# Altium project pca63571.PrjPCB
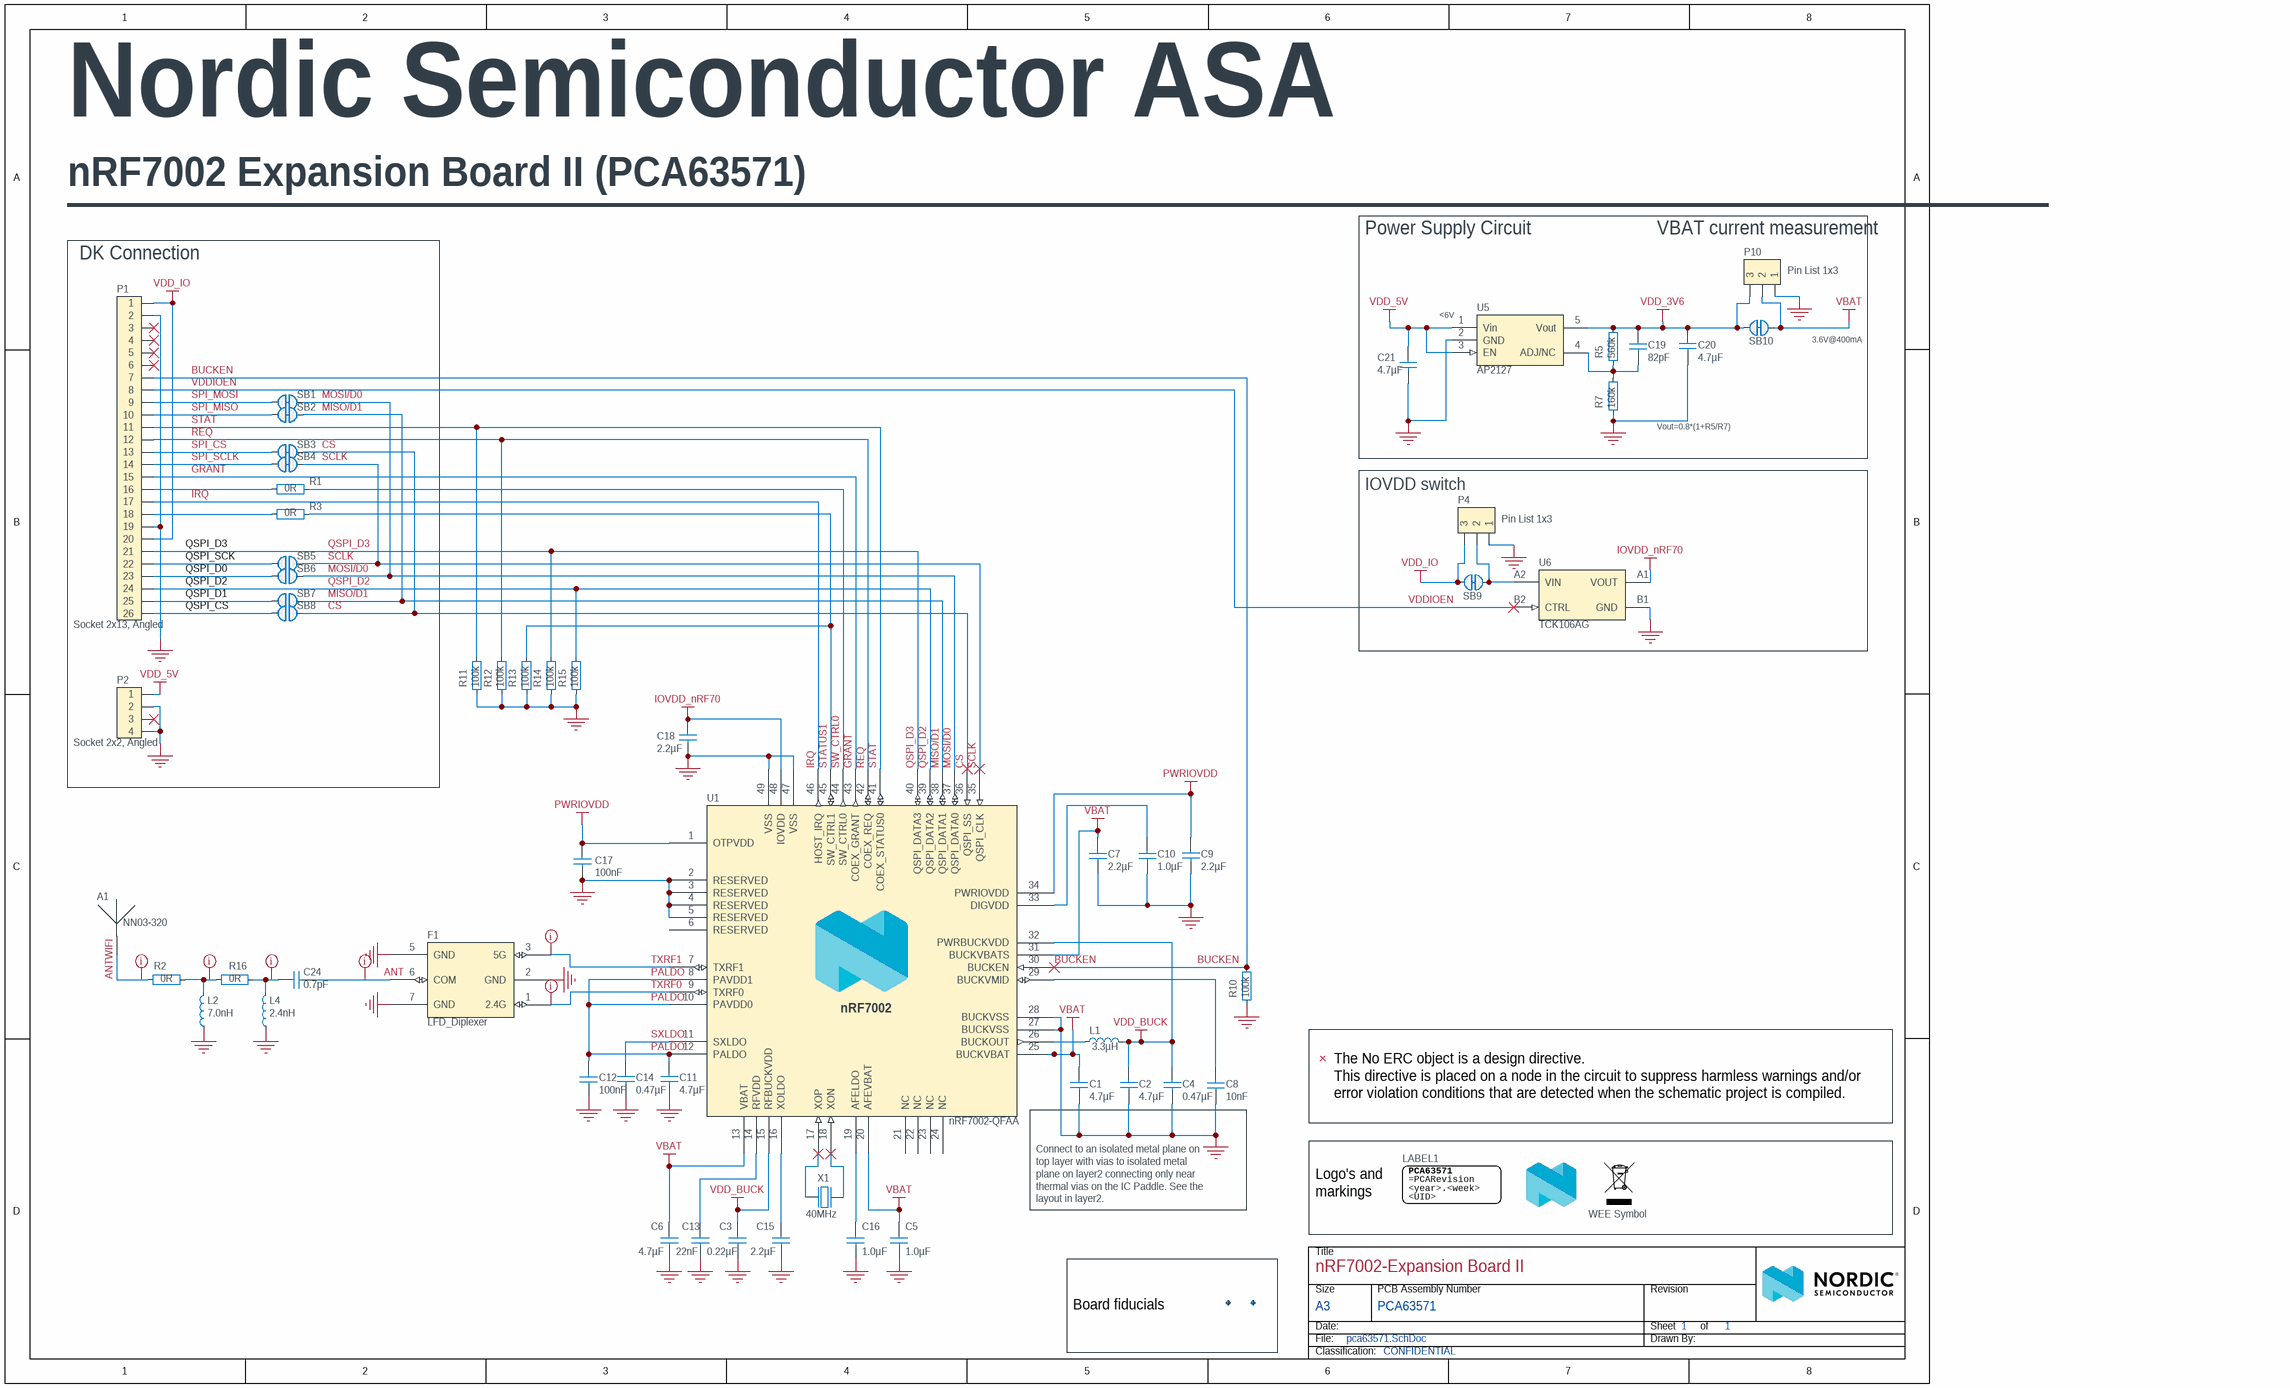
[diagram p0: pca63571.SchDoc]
BoardThickness: 1.6mm; BoardTitle: nRF7002 Expansion Board II; Classification: CONFIDENTIAL; Compliance: RoHS, REACH, Halogen-Free; Designer: HANY; Dielectric: FR-4; NrOfLayers: 4; Organization: Nordic Semiconductor; PCAName: PCA63571; PCARevision: 0.5.0; PCBNumber: 400902; PCBRevision: 0069HANY; PCBStackup: 4001; ProductName: nRF7002-EB2; ProjectName: nRF7002 EXpansion Board II; ProjectNumber: 4486; SilkscreenColor: White; SoldermaskColor: Blue; SurfaceFinish: ENIG Gold
1 sheet, 62 parts. Net scope: global (net labels, ports and power ports of the same name join across sheets).
Board files: 400902.PcbDoc, 400902_panel.PcbDoc

## Sheet pca63571.SchDoc: nRF7002-Expansion Board II
size A3; Organization: Nordic Semiconductor; Revision: 0.5.0; SheetNumber: 1; SheetTotal: 1; Author: HANY; CompanyName: Nordic Semiconductor; DrawnBy: HANY; DocumentSize: A4

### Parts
A1  NN03-320  [NN03-320]
C1  4.7µF  [CAPC1608X06L]
C2  4.7µF  [CAPC1608X06L]
C3  0.22µF  [CAPC0603X03L_C]
C4  0.47µF  [CAPC0603X03L_C]
C5  1.0µF  [CAPC1005X04L]
C6  4.7µF  [CAPC1608X06L]
C7  2.2µF  [CAPC1608X06L]
C8  10nF  [CAPC0603X03L_C]
C9  2.2µF  [CAPC1005X04L]
C10  1.0µF  [CAPC1005X04L]
C11  4.7µF  [CAPC1608X06L]
C12  100nF  [CAPC0603X03L_C]
C13  22nF  [CAPC0603X03L_C]
C14  0.47µF  [CAPC0603X03L_C]
C15  2.2µF  [CAPC0603X03L_C]
C16  1.0µF  [CAPC1005X04L]
C17  100nF  [CAPC0603X03L_C]
C18  2.2µF  [CAPC1608X06L]
C19  82pF  [CAPC0603X03L_C]
C20  4.7µF  [CAPC1608X06L]
C21  4.7µF  [CAPC1608X06L]
C24  0.7pF  [CAPC1005X04L]
F1  LFD_Diplexer  [CAF-50P160X80-6N]
Fid1  Fiducial mark  [Fiducial]  (value not drawn)  (no BOM)
Fid2  Fiducial mark  [Fiducial]  (value not drawn)  (no BOM)
L1  3.3µH  [INDC2520X10N]
L2  7.0nH  [INDC1005X04L_WW]
L4  2.4nH  [INDC1005X04L_WW]
LABEL1  12x32mm  [LabelSilk_12x32]  (value not drawn)
LOGO1  (no value)  [NORDIC_LOGO_LYING]  (graphical)
LOGO2  WEE Symbol  [WEEE_3x4.5mm]  (no BOM)
P1  Socket 2x13, Angled  [SOCKET_ANG_2x13_SMD-2.54mm-Mirrored]
P2  Socket 2x2, Angled  [WCON_2185-202ZSxCYNRX-Mirrored]
P4  Pin List 1x3  [LIST_1x3]
P10  Pin List 1x3  [LIST_1x3]
R1  0R  [RESC1005X04L]
R2  0R  [RESC1005X04L]
R3  0R  [RESC1005X04L]
R5  560k  [RESC0603X03L_C]
R7  160k  [RESC0603X03L_C]
R10  100k  [RESC0603X03L_C]
R11  100k  [RESC0603X03L_C]
R12  100k  [RESC0603X03L_C]
R13  100k  [RESC0603X03L_C]
R14  100k  [RESC0603X03L_C]
R15  100k  [RESC0603X03L_C]
R16  0R  [RESC1005X04L]
SB1  Solderbridge  [Solderbridge_SHORTED_0.4]  (value not drawn)  (net tie, no BOM)
SB2  Solderbridge  [Solderbridge_SHORTED_0.4]  (value not drawn)  (net tie, no BOM)
SB3  Solderbridge  [Solderbridge_SHORTED_0.4]  (value not drawn)  (net tie, no BOM)
SB4  Solderbridge  [Solderbridge_SHORTED_0.4]  (value not drawn)  (net tie, no BOM)
SB5  Solderbridge  [Solderbridge_0.4]  (value not drawn)  (no BOM)
SB6  Solderbridge  [Solderbridge_0.4]  (value not drawn)  (no BOM)
SB7  Solderbridge  [Solderbridge_0.4]  (value not drawn)  (no BOM)
SB8  Solderbridge  [Solderbridge_0.4]  (value not drawn)  (no BOM)
SB9  Solderbridge  [Solderbridge_Shorted_Power]  (value not drawn)  (net tie, no BOM)
SB10  Solderbridge  [Solderbridge_Shorted_Power]  (value not drawn)  (net tie, no BOM)
U1  nRF7002-QFAA  [QFN40P600X600X60-48N]
U5  AP2127  [SOT95P282X145-5N]
U6  TCK106AG  [BGA4C40P2X2_76X76X62]
X1  40MHz  [BT-XTAL_1612]

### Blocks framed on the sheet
DK Connection: P1 P2 R1 R3 SB1-SB8
IOVDD switch: P4 SB9 U6

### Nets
GND: C1.1 C2.1 C3.1 C4.1 C5.1 C6.1 C7.2 C8.2 C9.1 C10.2 C11.1 C12.2 C13.1 C14.1 C15.1 C16.1 C17.1 C18.1 C20.1 C21.1 F1.2(GND) F1.5(GND) F1.7(GND) L2.1 L4.1 P1.2 P1.19 P2.2 P2.4 P4.1 P10.1 R7.1 R10.2 R11.2 R12.2 R13.1 R14.2 R15.2 U1.2(RESERVED) U1.3(RESERVED) U1.4(RESERVED) U1.5(RESERVED) U1.27(BUCKVSS) U1.28(BUCKVSS) U1.47(VSS) U1.49(VSS) U5.2(GND) U6.B1(GND) X1.2(GND) X1.4(GND)
IOVDD_nRF70: C18.2 U1.48(IOVDD) U6.A1(VOUT)
PWRIOVDD: C9.2 C17.2 U1.1(OTPVDD) U1.34(PWRIOVDD)
VBAT: C1.2 C5.2 C6.2 C7.1 P10.2 SB10.2 U1.13(VBAT) U1.20(AFEVBAT) U1.25(BUCKVBAT) U1.31(BUCKVBATS)
VDD_3V6: C19.1 C20.2 P10.3 R5.2 SB10.1 U5.5(Vout)
VDD_5V: C21.2 P2.1 U5.1(Vin) U5.3(EN)
VDD_BUCK: C2.2 C3.2 C4.2 L1.2 U1.15(RFBUCKVDD) U1.32(PWRBUCKVDD)
VDD_IO: P1.1 P1.20 P4.3 SB9.2
ANT: C24.2 F1.6(COM)
ANTWIFI: A1.4(Feed1) R2.1
BUCKEN: P1.7 R10.1 U1.30(BUCKEN)
CS: SB3.1 SB8.1 U1.36(QSPI_SS)
GRANT: P1.15 U1.43(COEX_GRANT)
IRQ: P1.17 U1.46(HOST_IRQ)
MISO/D1: SB2.1 SB7.1 U1.38(QSPI_DATA1)
MOSI/D0: SB1.1 SB6.1 U1.37(QSPI_DATA0)
PALDO: C11.2 C12.1 U1.8(PAVDD1) U1.10(PAVDD0) U1.12(PALDO)
QSPI_D2: P1.24 R15.1 U1.39(QSPI_DATA2)
QSPI_D3: P1.21 R14.1 U1.40(QSPI_DATA3)
REQ: P1.12 R12.1 U1.42(COEX_REQ)
SCLK: SB4.1 SB5.1 U1.35(QSPI_CLK)
SPI_CS: P1.13 SB3.2
SPI_MISO: P1.10 SB2.2
SPI_MOSI: P1.9 SB1.2
SPI_SCLK: P1.14 SB4.2
STAT: P1.11 R11.1 U1.41(COEX_STATUS0)
STATUS1: R3.2 R13.2 U1.45(SW_CTRL1)
SW_CTRL0: R1.2 U1.44(SW_CTRL0)
SXLDO: C14.2 U1.11(SXLDO)
TXRF0: F1.1(2.4G) U1.9(TXRF0)
TXRF1: F1.3(5G) U1.7(TXRF1)
VDDIOEN: P1.8 U6.B2(CTRL)
NetC8_1: C8.1 U1.29(BUCKVMID)
NetC10_1: C10.1 U1.33(DIGVDD)
NetC13_2: C13.2 U1.14(RFVDD)
NetC15_2: C15.2 U1.16(XOLDO)
NetC16_2: C16.2 U1.19(AFELDO)
NetC19_2: C19.2 R5.1 R7.2 U5.4(ADJ/NC)
NetC24_1: C24.1 L4.2 R16.2
NetL1_1: L1.1 U1.26(BUCKOUT)
NetL2_2: L2.2 R2.2 R16.1
NetP1_16: P1.16 R1.1
NetP1_18: P1.18 R3.1
NetP1_22: P1.22 SB5.2
NetP1_23: P1.23 SB6.2
NetP1_25: P1.25 SB7.2
NetP1_26: P1.26 SB8.2
NetP4_2: P4.2 SB9.1 U6.A2(VIN)
NetU1_17: U1.17(XOP) X1.1(inp)
NetU1_18: U1.18(XON) X1.3(out)

Not connected (* = marked no-connect by the designer): A1 1(NC) 2(GND) 3(Feed2); P1 3* 4* 5* 6*; P2 3*; U1 6(RESERVED) 21(NC) 22(NC) 23(NC) 24(NC)

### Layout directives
net class RF: ANT, ANTWIFI, NetC24_1, NetL2_2, TXRF0, TXRF1

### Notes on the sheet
- Nordic Semiconductor ASA
- nRF7002 Expansion Board II (PCA63571)
- _______________________________________________________________________
- Power Supply Circuit
- (near P10) VBAT current measurement
- (near U5) <6V
- 3.6V@400mA
- Vout=0.8*(1+R5/R7)
- QSPI_D2
- QSPI_D3
- QSPI_SCK
- QSPI_D0
- QSPI_D1
- QSPI_CS
- The No ERC object is a design directive.
  This directive is placed on a node in the circuit to suppress harmless warnings and/or error violation conditions that are detected when the schematic project is compiled.
- (near U1) Connect to an isolated metal plane on top layer with vias to isolated metal plane on layer2 connecting only near thermal vias on the IC Paddle. See the layout in layer2.
- (near LABEL1) Logo's and markings
- (near Fid1) Board fiducials

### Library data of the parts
A1 = NN03-320: Dual-Band GNSS and Wi-Fi/BluetoothAntenna; Manufacturer: Ignion; Part number NEMS: 100700066; Component Status: Active; Pad Count: 4; Note: N.A.
C1 C2 C6 C11 = C0603-4µ7-25V-X6S-GRM188C81E475KE11: Capacitor, Ceramic, 4.7µF 25V X6S 0603,±10%; Manufacturer: Murata; Manufacturer Part Number: GRM188C81E475KE11D; Part number NEMS: 100200486; Pad Count: 2; Artikkelnr Noca: N.A.; Component Status: Active
C3 = C0201-220n-10V-X5R-GRM033R61A224KE90: Capacitor, Ceramic, 0.22µF 10V X5R 0201, ±10%; Manufacturer: Murata; Manufacturer Part Number: GRM033R61A224KE90D; Part number NEMS: 100200487; Pad Count: 2; Artikkelnr Noca: N.A.; Component Status: Active
C4 C14 = C0201-470n-6.3V-X5R-GRM033R60J474KE90: Capacitor, Ceramic, 0.47µF 6.3V X5R 0201,±10%; Manufacturer: Murata; Manufacturer Part Number: GRM033R60J474KE90D; Part number NEMS: 100200488; Pad Count: 2; Artikkelnr Noca: N.A.; Component Status: Active
C5 = C0402-1µ0-35V-X5R-GRM155R6YA105KE11: Capacitor, Ceramic, 1.0µF 35V X5R 0402,±10%; Manufacturer: Murata; Manufacturer Part Number: GRM155R6YA105KE11D; Part number NEMS: 100200489; Pad Count: 2; Artikkelnr Noca: N.A.; Component Status: Active
C7 C18 = C0603-2µ2-16V-X7S-GRM188C71C225KE11: Capacitor, Ceramic, 2.2µF 16V X7S 0603,±10%; Manufacturer: Murata; Manufacturer Part Number: GRM188C71C225KE11D; Part number NEMS: 100200490; Pad Count: 2; Artikkelnr Noca: N.A.; Component Status: Active
C8 = C0201-10n-16V-X7R-GRM033R71C103KE14: Capacitor, Ceramic, 10nF 16V X7R 0201,±10%; Manufacturer: Murata; Manufacturer Part Number: GRM033R71C103KE14D; Part number NEMS: 100200491; Pad Count: 2; Artikkelnr Noca: N.A.; Component Status: Active
C9 = C0402-2µ2-25V-X5R-GRM155R61E225KE11: Capacitor, Ceramic, 2.2µF 25V X5R 0402,±10%; Manufacturer: Murata; Manufacturer Part Number: GRM155R61E225KE11D; Part number NEMS: 100200492; Pad Count: 2; Artikkelnr Noca: N.A.; Component Status: Active
C10 = C0402-1µ0-16V-X6S-GRM155C81C105KE11D: Capacitor, Ceramic, 1.0µF 16V X6S 0402,±10%; Manufacturer: Murata; Part number NEMS: 100200516; Pad Count: 2; Artikkelnr Noca: N.A.; Component Status: Active
C12 C17 = C0201-100n-16V-X7S-GRM033C71C104KE14: Capacitor, Ceramic, 100nF 16V X7S 0201,±10%; Manufacturer: Murata; Manufacturer Part Number: GRM033C71C104KE14D; Part number NEMS: 100200494; Pad Count: 2; Artikkelnr Noca: N.A.; Component Status: Active
C13 = C0201-22n-10V-X5R-GRM033R61A223KE84: Capacitor, Ceramic, 22nF 10V X5R 0201,±10%; Manufacturer: Murata; Manufacturer Part Number: GRM033R61A223KE84D; Part number NEMS: 100200495; Pad Count: 2; Artikkelnr Noca: N.A.; Component Status: Active
C15 = C0201-2µ2-10V-X5R-GRM033R61A225KE47: Capacitor, Ceramic, 2.2µF 10V X5R 0201,±10%; Manufacturer: Murata; Manufacturer Part Number: GRM033R61A225KE47D; Part number NEMS: 100200496; Pad Count: 2; Artikkelnr Noca: N.A.; Component Status: Active
C16 = C0402-1µ0-10V-X7S-GRM155C71A105KE11: Capacitor, Ceramic, 1.0µF 10V X7S 0402,±10%; Manufacturer: Murata; Manufacturer Part Number: GRM155C71A105KE11D; Part number NEMS: 100200497; Pad Count: 2; Artikkelnr Noca: N.A.; Component Status: Active
C19 = C0201-82p: Chip Cap 0201; Manufacturer: N.A.; Part number NEMS: 100200043; Pad Count: 2; Note: Chip Cap 1%; Component Status: Active
C20 C21 = C0603-4.7µ-10V-X7R: Capacitor, MLCC; Manufacturer: Murata; Manufacturer Part Number: GRM188Z71A475KE15J; Part number NEMS: 100200438; Pad Count: 2; Note: 10V; Artikkelnr Noca: N.A.; Component Status: Active
C24 = C0402-0.7p-50V-C0G-GJM1555C1HR70WB01: Capacitor, C0G/NP0, 50V, ±0.05pF, 0402; Manufacturer: Murata; Manufacturer Part Number: GJM1555C1HR70WB01D; Part number NEMS: 100200707; Component Status: Active; Pad Count: 2; Artikkelnr Noca: N.A.
F1 = LFD182G45DCJD247: Signal Conditioning 2.4GHz and 5GHz Diplexer; Manufacturer: Murata; Part number NEMS: 100800026; Pad Count: 6; Note: N.A.; Component Status: Active
Fid1 Fid2 = Fid-Mark: Manufacturer: N.A.; Part number NEMS: 100500073; Value: N.A.; Pad Count: 1; Component Status: Active; System: Connector
L1 = L1008-3µ3-LQM2HPN3R3MGCL: Inductor, 1A, ±20%, 200mOhm; Manufacturer: Murata; Part number NEMS: 100300406; Pad Count: 2; Note: -55°C ~ 125°C; Artikkelnr Noca: N.A.; Component Status: Active
L2 = L0402-7n0-Wirewound-Murata: Inductor, 570mA, ±2%, 130mΩ; Manufacturer: Murata; Manufacturer Part Number: LQW15AN7N0G00; Part number NEMS: 100300337; Component Status: Active; Pad Count: 2; Note: -55°C ~ 125°C; Artikkelnr Noca: N.A.
L4 = L0402-2n4-Wirewound-LQW15AN_80: Inductor, 2.53A, 2%, 22mΩ, Q=30; Manufacturer: Murata; Manufacturer Part Number: LQW15AN2N4G80; Part number NEMS: 100300507; Component Status: Active; Pad Count: 2; Note: -55°C ~ 125°C; Artikkelnr Noca: N.A.
LABEL1 = Label_12x32: PCA version label, stick-on, 12x32mm; Manufacturer: Ellco Etikett; Manufacturer Part Number: 68616; Part number NEMS: 101200029; Component Status: Active; Pad Count: 0; Note: N.A.
LOGO1 = Nordic Logo lying: Manufacturer: N.A.; Part number NEMS: 101100001; Component Status: Active; Pad Count: 0
LOGO2 = WEEE Symbol 3x4.5mm: WEEE Directive symbol; Manufacturer: N.A.; Part number NEMS: 101100006; Component Status: Active; Pad Count: 0
P1 = 2185-213ZG0CYNR3: Socket 2x13, 2.54mm (100mil), Right Angle, SMD; Manufacturer: WCON; Part number NEMS: 100500914; Component Status: Active; Pad Count: 26; Note: N.A.; System: Connector
P2 = 2185-202ZS0CYNR3: Socket 2x2, 2.54mm (100mil), Right Angle, SMD; Manufacturer: WCON; Part number NEMS: 100500857; Component Status: Active; Pad Count: 4; Note: N.A.; System: Connector
P4 P10 = Pin List 1x3: Pin List 1x3, 2.54mm (100mil); Manufacturer: N.A.; Part number NEMS: 100500304; Component Status: Active; Pad Count: 3; Artikkelnr Noca: 56019041; System: Connector
R1-R3 R16 = R0402-0R: Resistor, ±5%, 0.063W; Manufacturer: N.A.; Part number IPS: 00000007128; Part number NEMS: 100100109; Component Status: Active; Pad Count: 2; Note: Chip Res 5%; Artikkelnr Noca: 27049000
R5 = R0201-560k: Resistor, ±1%, 0.05W; Manufacturer: N.A.; Part number IPS: 00000004799; Part number NEMS: 100100090; Note: Chip Res 1%; Pad Count: 2; Component Status: Active
R7 = R0201-160k: Resistor, ±1%, 0.05W; Manufacturer: N.A.; Part number NEMS: 100100657; Note: Chip Res 1%; Pad Count: 2; Component Status: Active
R10-R15 = R0201-100k: Resistor, ±1%, 0.05W; Manufacturer: N.A.; Part number IPS: 00000001419; Part number Norautron: 26108487; Part number NEMS: 100100080; Note: Chip Res 1%; Pad Count: 2; Component Status: Active
SB1-SB4 = Solderbridge Shorted 0.4mm: Shorted Solderbridge; Manufacturer: N.A.; Part number NEMS: 100500561; Component Status: Active; Pad Count: 2; System: Connector
SB5-SB8 = Solderbridge 0.4mm: Manufacturer: N.A.; Part number NEMS: 100500560; Component Status: Active; Pad Count: 2; System: Connector
SB9 SB10 = Solderbridge Shorted Power: Shorted Solderbridge Power; Manufacturer: N.A.; Part number NEMS: 100500460; Pad Count: 2; Component Status: Active; System: Connector
U1 = nRF7002-QFAAB0: Wi-fi Dual Band Companion chip; Manufacturer: Nordic Semiconductor; Part number NEMS: 102000276; Pad Count: 49; Note: N.A.; Component Status: Active
U5 = AP2127K-ADJTRG1: IC REG LDO ADJ 0.3A SOT23-5; Manufacturer: Diodes Incorporated; Part number NEMS: 101900493; Pad Count: 5; Note: N.A.; Component Status: Active
U6 = TCK106AG: 1.0 A Load Switch IC with Slew Rate Control Driver in Ultra Small Package; Manufacturer: Toshiba; Manufacturer Part Number: TCK106AG,LF; Part number IPS: 00000004390; Part number Norautron: 26500627; Part number NEMS: 101900575; Note: N.A.; Pad Count: 4; Component Status: Active
X1 = XTAL_SMD1612_40MHz_8pF_Kyocera: XTAL SMD 1612, 40MHz, Cl=8pF, Total Tol: ±10ppm, -30 - 85C; Manufacturer Part Number: CX1612DB40000D0WLLCC; Part number NEMS: 101600104; Component Status: Active; Pad Count: 4; Note: XTAL SMD 40.000MHz 8pF; Artikkelnr Noca: N.A.

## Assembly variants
Default: not fitted P4 P10 R1 R3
